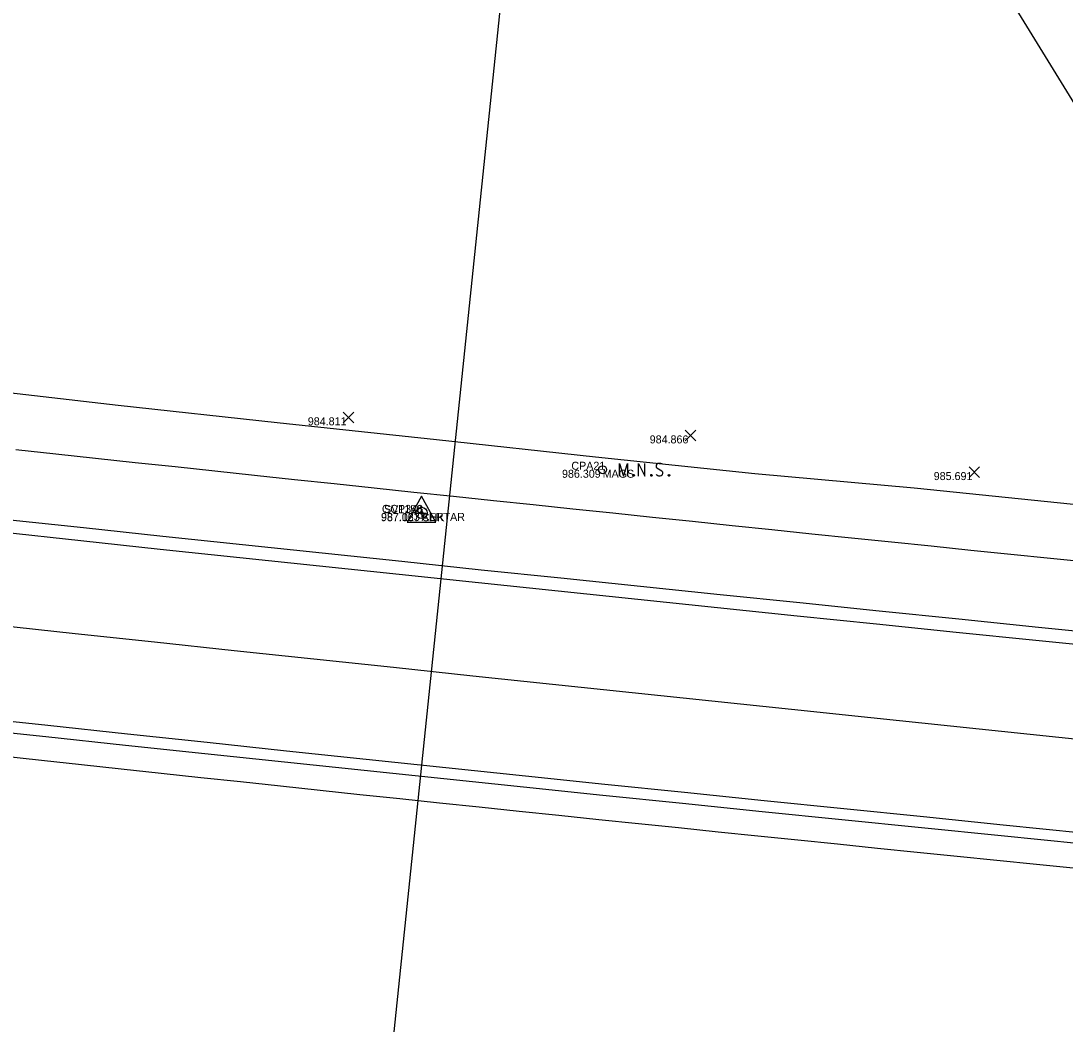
# Model space of a CAD drawing. Extents: x 2065431 to 2068157, y 709104 to 709719.
# Drawn here: x 2067248 to 2067378.4, y 709378.9 to 709504.2 of the extents above; entities that cross this region are included whole.
import ezdxf

# ---------------------------------------------------------------- set-up
doc = ezdxf.new("R2010")
doc.units = 0
for name, color, linetype in [('DR_X_Storm_Sewer', 7, 'Continuous'), ('DT_X_Break_Line', 7, 'Continuous'), ('DT_X_Terrain_Boundary', 7, 'Continuous'), ('PM_X_Edge_Line', 7, 'Continuous'), ('PM_X_Lane_Line', 7, 'Continuous'), ('PV_X_EOP', 7, 'Continuous'), ('PV_X_Shoulder_Rumble_Strip', 7, 'Continuous'), ('RS_Raster1', 7, 'Continuous'), ('RW_X_CL_100_Bearings', 7, 'Continuous'), ('RW_X_CL_100_Curve_Data', 7, 'Continuous'), ('SV_P_Aerial_Targets', 7, 'Continuous'), ('SV_X_Mon_Cells_Found', 7, 'Continuous'), ('SV_X_Text_Elevation', 7, 'Continuous'), ('SV_X_Text_Name', 7, 'Continuous')]:
    doc.layers.add(name, color=color, linetype=linetype)

msp = doc.modelspace()

# ---------------------------------------------------------------- linework, layer by layer
at = {"layer": 'DR_X_Storm_Sewer'}
msp.add_line((2067313.91, 709564.11), (2067272.26, 709162.87), dxfattribs=at)
at = {"layer": 'DT_X_Break_Line'}
msp.add_lwpolyline([(2067498.75, 709430.51), (2067478.87, 709432.67), (2067458.99, 709434.82), (2067439.1, 709436.98), (2067419.22, 709439.13), (2067399.35, 709441.43), (2067379.49, 709443.77), (2067359.59, 709445.77), (2067339.67, 709447.56), (2067319.78, 709449.65), (2067299.9, 709451.81), (2067280.01, 709453.96), (2067260.13, 709456.11), (2067240.26, 709458.41), (2067220.42, 709460.94), (2067200.58, 709463.45), (2067180.69, 709465.52), (2067160.8, 709467.59), (2067140.91, 709469.71), (2067125.91, 709471.33)], dxfattribs=at)
at = {"layer": 'DT_X_Terrain_Boundary'}
msp.add_lwpolyline([(2067560.73, 709418.79), (2067495.34, 709436.29), (2067456.65, 709439.38), (2067410.67, 709443.42), (2067361.02, 709524.1), (2067366.41, 709549.95), (2067373.99, 709596.43), (2067354.6, 709616.29), (2067311.55, 709621.56), (2067309.4, 709622.8), (2067308.24, 709625.52), (2067305.17, 709625.78), (2067302.95, 709628.43), (2067239.24, 709621.32), (2067197.78, 709611.01), (2067153.08, 709612.99), (2067144.2, 709539.81), (2067080.32, 709510.92)], dxfattribs=at)
at = {"layer": 'PM_X_Edge_Line'}
for points in [[(2067245.5, 709440.32), (2067255.44, 709439.26), (2067265.39, 709438.19), (2067275.33, 709437.13), (2067285.27, 709436.08), (2067295.22, 709435.03), (2067305.16, 709433.99), (2067315.11, 709432.95), (2067325.06, 709431.91), (2067335, 709430.88), (2067344.95, 709429.85), (2067354.9, 709428.83), (2067364.85, 709427.82), (2067374.8, 709426.8), (2067384.74, 709425.8)], [(2067241.4, 709417.25), (2067251.34, 709416.18), (2067261.28, 709415.12), (2067271.23, 709414.06), (2067281.17, 709413), (2067291.12, 709411.96), (2067301.06, 709410.91), (2067311.01, 709409.87), (2067320.95, 709408.84), (2067330.9, 709407.82), (2067340.85, 709406.79), (2067350.8, 709405.78), (2067360.75, 709404.77), (2067370.69, 709403.76), (2067380.64, 709402.76)]]:
    msp.add_lwpolyline(points, dxfattribs=at)
at = {"layer": 'PM_X_Lane_Line'}
msp.add_lwpolyline([(2067244.79, 709428.71), (2067254.74, 709427.65), (2067264.68, 709426.59), (2067274.62, 709425.53), (2067284.57, 709424.48), (2067294.51, 709423.42), (2067304.46, 709422.37), (2067314.4, 709421.32), (2067324.35, 709420.27), (2067334.29, 709419.23), (2067344.24, 709418.19), (2067354.18, 709417.15), (2067364.13, 709416.11), (2067374.07, 709415.07), (2067384.02, 709414.04)], dxfattribs=at)
at = {"layer": 'PV_X_EOP'}
for points in [[(2067247.34, 709450.62), (2067252.32, 709450.08), (2067257.29, 709449.55), (2067262.26, 709449.01), (2067267.23, 709448.48), (2067272.2, 709447.95), (2067277.17, 709447.42), (2067282.14, 709446.89), (2067287.12, 709446.36), (2067292.09, 709445.83), (2067297.06, 709445.31), (2067302.03, 709444.78), (2067307.01, 709444.26), (2067311.98, 709443.73), (2067316.95, 709443.21), (2067321.92, 709442.69), (2067326.9, 709442.17), (2067331.87, 709441.65), (2067336.84, 709441.14), (2067341.82, 709440.62), (2067346.79, 709440.1), (2067351.76, 709439.59), (2067356.74, 709439.08), (2067361.71, 709438.57), (2067366.68, 709438.06), (2067371.66, 709437.55), (2067376.63, 709437.04), (2067381.61, 709436.53)], [(2067245.59, 709412.37), (2067250.56, 709411.83), (2067255.53, 709411.28), (2067260.5, 709410.75), (2067265.48, 709410.21), (2067270.45, 709409.67), (2067275.42, 709409.14), (2067280.39, 709408.61), (2067285.36, 709408.08), (2067290.33, 709407.55), (2067295.31, 709407.02), (2067300.28, 709406.5), (2067305.25, 709405.98), (2067310.22, 709405.46), (2067315.2, 709404.94), (2067320.17, 709404.42), (2067325.14, 709403.9), (2067330.12, 709403.39), (2067335.09, 709402.88), (2067340.06, 709402.36), (2067345.04, 709401.86), (2067350.01, 709401.35), (2067354.99, 709400.84), (2067359.96, 709400.34), (2067364.94, 709399.84), (2067369.91, 709399.34), (2067374.89, 709398.84), (2067379.86, 709398.34)]]:
    msp.add_lwpolyline(points, dxfattribs=at)
at = {"layer": 'PV_X_Shoulder_Rumble_Strip'}
for points in [[(2067245.83, 709441.93), (2067255.77, 709440.87), (2067265.71, 709439.81), (2067275.66, 709438.75), (2067285.6, 709437.7), (2067295.55, 709436.66), (2067305.49, 709435.61), (2067315.44, 709434.58), (2067325.39, 709433.54), (2067335.33, 709432.51), (2067345.28, 709431.49), (2067355.23, 709430.47), (2067365.18, 709429.46), (2067375.13, 709428.44), (2067385.07, 709427.44)], [(2067241.14, 709415.82), (2067251.08, 709414.76), (2067261.03, 709413.7), (2067270.97, 709412.64), (2067280.92, 709411.59), (2067290.86, 709410.55), (2067300.81, 709409.51), (2067310.75, 709408.48), (2067320.7, 709407.45), (2067330.65, 709406.43), (2067340.6, 709405.41), (2067350.54, 709404.4), (2067360.49, 709403.39), (2067370.44, 709402.39), (2067380.39, 709401.39)]]:
    msp.add_lwpolyline(points, dxfattribs=at)
at = {"layer": 'RS_Raster1'}
for p, q in [((2067297.56, 709442.66), (2067298.56, 709442.66)), ((2067298.06, 709443.16), (2067298.06, 709442.16)), ((2067298.06, 709442.66), (2067298.06, 709442.66))]:
    msp.add_line(p, q, dxfattribs=at)
at = {"layer": 'RW_X_CL_100_Bearings'}
for p, q in [((2067288.24, 709453.97), (2067289.57, 709455.3)), ((2067288.24, 709455.3), (2067289.57, 709453.97)), ((2067330.98, 709451.71), (2067332.31, 709453.05)), ((2067330.98, 709453.05), (2067332.31, 709451.71)), ((2067366.44, 709447.13), (2067367.77, 709448.47)), ((2067366.44, 709448.47), (2067367.77, 709447.13))]:
    msp.add_line(p, q, dxfattribs=at)
at = {"layer": 'RW_X_CL_100_Curve_Data'}
for points in [[(2067322.75, 709447.29), (2067322.75, 709448.89), (2067323.26, 709447.29), (2067323.75, 709448.89), (2067323.75, 709447.29)], [(2067325.12, 709447.29), (2067325.12, 709448.89), (2067325.95, 709447.29), (2067325.95, 709448.89)], [(2067328.1, 709448.78), (2067328.08, 709448.81), (2067328.04, 709448.83), (2067327.95, 709448.87), (2067327.82, 709448.89), (2067327.74, 709448.89), (2067327.7, 709448.89), (2067327.56, 709448.86), (2067327.44, 709448.78), (2067327.36, 709448.68), (2067327.34, 709448.58), (2067327.34, 709448.5), (2067327.36, 709448.4), (2067327.45, 709448.31), (2067328.06, 709447.94), (2067328.11, 709447.89), (2067328.13, 709447.84), (2067328.15, 709447.76), (2067328.15, 709447.68), (2067328.14, 709447.61), (2067328.13, 709447.56), (2067328.11, 709447.49), (2067328.09, 709447.44), (2067328.07, 709447.41), (2067328.03, 709447.37), (2067328, 709447.34), (2067327.96, 709447.32), (2067327.92, 709447.31), (2067327.82, 709447.29), (2067327.67, 709447.29), (2067327.57, 709447.32), (2067327.43, 709447.41), (2067327.34, 709447.48)], [(2067324.52, 709447.51), (2067324.57, 709447.51), (2067324.61, 709447.48), (2067324.64, 709447.43), (2067324.64, 709447.37), (2067324.61, 709447.32), (2067324.57, 709447.29), (2067324.52, 709447.29), (2067324.48, 709447.32), (2067324.45, 709447.37), (2067324.45, 709447.43), (2067324.48, 709447.48), (2067324.52, 709447.51)], [(2067326.73, 709447.51), (2067326.79, 709447.51), (2067326.82, 709447.48), (2067326.85, 709447.43), (2067326.85, 709447.37), (2067326.82, 709447.32), (2067326.79, 709447.29), (2067326.73, 709447.29), (2067326.7, 709447.32), (2067326.67, 709447.37), (2067326.67, 709447.43), (2067326.7, 709447.48), (2067326.73, 709447.51)], [(2067328.92, 709447.51), (2067328.97, 709447.51), (2067329, 709447.48), (2067329.04, 709447.43), (2067329.04, 709447.37), (2067329, 709447.32), (2067328.97, 709447.29), (2067328.92, 709447.29), (2067328.88, 709447.32), (2067328.85, 709447.37), (2067328.85, 709447.43), (2067328.88, 709447.48), (2067328.92, 709447.51)]]:
    msp.add_lwpolyline(points, dxfattribs=at)
msp.add_circle((2067320.66, 709448.09), 0.497, dxfattribs=at)
at = {"layer": 'SV_P_Aerial_Targets'}
msp.add_lwpolyline([(2067296.23, 709441.55), (2067299.83, 709441.55), (2067298.03, 709444.77)], close=True, dxfattribs=at)
for radius in [0.7, 0.16]:
    msp.add_circle((2067298.03, 709442.7), radius, dxfattribs=at)

# ---------------------------------------------------------------- texts
at = {"layer": 'SV_X_Mon_Cells_Found'}
for s, p in [('CPA21', (2067316.75, 709448.09)), ('GCP348', (2067293.08, 709442.7)), ('SV1150', (2067293.35, 709442.66))]:
    msp.add_text(s, height=1, dxfattribs=at).set_placement(p)
at = {"layer": 'SV_X_Text_Elevation'}
for s, p in [('MAGS', (2067320.66, 709447.09)), ('AERTAR', (2067298.03, 709441.7)), ('CHK', (2067298.06, 709441.66))]:
    msp.add_text(s, height=1, dxfattribs=at).set_placement(p)
at = {"layer": 'SV_X_Text_Name'}
for s, p in [('984.811', (2067283.82, 709453.64)), ('984.866', (2067326.54, 709451.38)), ('986.309', (2067315.58, 709447.09)), ('985.691', (2067362.03, 709446.8)), ('987.123', (2067292.97, 709441.7)), ('987.067', (2067292.96, 709441.66))]:
    msp.add_text(s, height=1, dxfattribs=at).set_placement(p)

doc.saveas('drawing.dxf')
